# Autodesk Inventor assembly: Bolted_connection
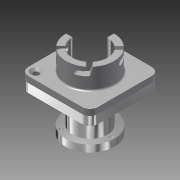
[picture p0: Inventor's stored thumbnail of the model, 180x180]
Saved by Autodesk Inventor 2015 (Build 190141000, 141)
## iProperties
Created: 2005-10
Part Number: Bolted_connection
Document SubType Name: Assembly
Designer: hassen
Mass: 715.183 g
Surface Area: 392.34 cm^2
Volume: 120.562 cm^3
Density: 5.93208 g/cm^3
Author: hassen
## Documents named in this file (3)
- C:\Users\Aielloj\Downloads\inventor_2014_mechanical_designs\tutorial files\Bolted Connection\Bolted_connection.iam
- C:\Users\Aielloj\Downloads\inventor_2014_mechanical_designs\tutorial files\Bolted Connection\Spindle.ipt
- C:\Users\Aielloj\Downloads\inventor_2014_mechanical_designs\tutorial files\Bolted Connection\basic_plate.ipt
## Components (2 placed, 2 different names)
1. Spindle:1 — Insert:1, Angle:1
2. basic_plate:1 — Insert:1, Angle:1
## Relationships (2: Insert 1, Angle 1)
- Insert:1: Spindle:1 ↔ basic_plate:1
- Angle:1: Spindle:1 ↔ basic_plate:1
